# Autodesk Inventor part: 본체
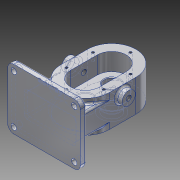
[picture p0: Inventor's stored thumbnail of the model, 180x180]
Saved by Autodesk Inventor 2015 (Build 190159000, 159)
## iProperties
Created: 2020-09
Part Number: 본체
Material: 알루미늄 6061
Document SubType Name: Modeling
Designer: LINEART-SSD.D4.16.06
Density: 2.7 g/cm^3
Appearance: 알루미늄 - 평지
Mass: 1442.27 g
Surface Area: 790.225 cm^2
Volume: 534.173 cm^3
Author: LINEART-SSD.D4.16.06
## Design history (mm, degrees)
sketch "스케치1"
  geometry: L1 (40, 152)-(0, 152); L2 (40, 152)-(80, 152); L3 (40, 90)-(40, 28); L4 (0, 28)-(80, 28); L5 (80, 28)-(80, 152); L6 (80, 152)-(0, 152); L7 (0, 152)-(0, 28); L8 (0, 28)-(80, 152); L9 (80, 28)-(0, 152); 1 further point
  constraints: 18 end point, 3 horizontal, 2 midpoint, 2 parallel, 1 perpendicular
  dimensions: "d7" = 40 distance of L1.start L1.end; "d8" = 40 distance of L1.start L2.end; "d9" = 62 distance of L3.start L3.end
extrude "돌출1" new body sketch "스케치1" distance "d10" = 53; taper "d11" = 0 deg
fillet "모깎기1" dims "d12" = 40
sketch "스케치2"
  geometry: L1 (80, 68)-(80, 112) reference; L2 (0, 112)-(0, 68) reference; L3 (16, 112)-(16, 68); L4 (64, 112)-(64, 68); A1 r 40 centre (40, 68) between (0, 68) and (80, 68) reference; A2 r 40 centre (40, 112) between (80, 112) and (0, 112) reference; A3 r 40 centre (40, 68) between (0, 68) and (80, 68) reference; A4 r 24 centre (40, 112) between (64, 112) and (16, 112); A5 r 24 centre (40, 68) between (16, 68) and (64, 68); 1 further point
  constraints: 4 end point, 4 point on circle, 2 centre point, 2 coincident, 2 tangent
  dimensions: "d40" = 48 diameter of A5
extrude "돌출2" cut sketch "스케치2" distance "d17" = 29; taper "d18" = 0 deg
node "작업 평면1"
sketch "스케치7"
  geometry: L1 (136, 53)-(136, 24) reference; L2 (112, 24)-(136, 24) reference; L3 (124.5, 24)-(124.5, 9); L4 (124.5, 9)-(120.5, 9); L5 (112, 0)-(112, 53) reference; L6 (120.5, 9)-(120.5, -9.7); L7 (120.5, -9.7)-(125.596, -9.7); L8 (112, -25.591)-(112, 0); L9 (126, -17)-(131, -17); L10 (124.5, 24)-(112, 24); L11 (152, 0)-(112, 0) reference; L12 (131, -17)-(131, 0); L13 (131, 0)-(120.5, 0); L14 (112, 24)-(112, 0); L15 (120.5, 0)-(112, 0); L16 (125.596, -9.7)-(126, -10.4); L17 (126, -10.4)-(126, -17); 1 further point
  constraints: 26 end point, 5 perpendicular, 4 point on line, 3 vertical, 1 collinear, 1 horizontal
  dimensions: "d42" = 15 distance between parallel lines of L4 L2; "d43" = 17 distance between parallel lines of L11 L9; "d44" = 7.3 distance between parallel lines of L7 L9; "d48" = 25 diameter of L3 L8; "d49" = 17 diameter of L6 L8; "d51" = 38 diameter of L12 L8; "d120" = 25.59078 distance from line of L8.start L11; "d147" = 0.7 vertical distance of L16.end L7.end; "d148" = 30 deg angle of L17 L16; "d149" = 28 diameter of L17 L8
revolve "회전4" sketch "스케치7" stored, may be unused: angle "d52" = 90 deg
sketch "스케치8"
  geometry: L1 (112, 24)-(136, 24) reference; L2 (120.5, 9)-(120.5, 0); L3 (152, 0)-(112, 0) reference; L4 (112, 24)-(112, 0); L5 (112, 0)-(112, 53) reference; L6 (120.5, 9)-(124.5, 9); L7 (124.5, 9)-(124.5, 24); 1 further point
  constraints: 8 end point, 2 point on line, 1 collinear, 1 horizontal, 1 perpendicular
  dimensions: "d53" = 25 diameter of L7 L4; "d54" = 17 diameter of L2 L4; "d55" = 15 distance between parallel lines of L1 L6
revolve "회전5" sketch "스케치8" stored, may be unused: angle "d56" = 90 deg
sketch "스케치9"
  geometry: L1 (44, 53)-(44, 24) reference; L2 (44, 24)-(68, 24) reference; L3 (56, 24)-(56, 4.58); L4 (68.5, 12.214)-(68.5, 4.58); L5 (68.5, 4.58)-(56, 4.58); L6 (68.5, 12.214)-(68.5, 24); L7 (68.5, 24)-(68, 24); L8 (68, 24)-(112, 24) reference; L9 (68, 24)-(68.5, 24); L10 (68, 24)-(56, 24); 1 further point
  constraints: 14 end point, 3 collinear, 3 vertical, 1 midpoint, 1 perpendicular
  dimensions: "d58" = 25 diameter of L4 L3; "d121" = 19.41962 distance between parallel lines of L8 L5; "d122" = 11.78565 distance from line of L4.start L2
sketch "스케치10"
  geometry: L1 (64, 112)-(64, 68) reference; L2 (16, 68)-(16, 112) reference; C1 r 12.5 at (40, 112) reference; C2 r 12.5 at (40, 112) reference; A1 r 24 centre (40, 68) between (16, 68) and (64, 68) reference; A2 r 24 centre (40, 112) between (64, 112) and (16, 112) reference; A3 r 31 centre (40, 68) between (9, 68) and (71, 68); 6 further points
  constraints: 3 point on circle, 2 coincident, 1 centre point, 1 vertical alignment
  dimensions: "d61" = 31 distance of C1.centre point (40, 143); "d69" = 31 radius of A3
hole "구멍1" sketch "스케치10" at (40, 143), (71, 112), (9, 112), (9, 68), (71, 68), (40, 37) diameter "d62" = 4.134; stored, may be unused: countersink angle "d66" = 90 deg, drill point angle "d68" = 118 deg; dims "d63" = 10, "d64" = 4, "d65" = 2, "d67" = 12
sketch "스케치11"
  geometry: L1 (0, 0)-(-53, 0) reference; L2 (0, 44)-(0, 0) reference; L3 (-53, 44)-(0, 44) reference; L4 (-53, 0)-(-53, 44) reference; L5 (-53, 0)-(0, 0) reference; L6 (0, 44)-(-53, 44) reference; L7 (0, -40)-(-53, -40) reference; C1 r 11 at (-39, 22); 1 further point
  constraints: 1 centre point
  dimensions: "d90" = 14 distance from line of C1.centre L4; "d91" = 22 distance from line of L1 C1.centre; "d92" = 22 diameter of C1
extrude "돌출3" join sketch "스케치11" distance "d72" = 10; taper "d73" = 0 deg
sketch "스케치12"
  geometry: L1 (53, 0)-(0, 0) reference; L2 (53, 44)-(53, 0) reference; L3 (0, 44)-(53, 44) reference; L4 (0, 0)-(0, 44) reference; C1 r 11 at (39, 22); 2 further points
  constraints: 1 centre point, 1 midpoint
  dimensions: "d93" = 14 distance from line of L2 C1.centre; "d94" = 22 distance from line of L1 C1.centre; "d95" = 22 diameter of C1
extrude "돌출4" join sketch "스케치12" distance "d77" = 10; taper "d78" = 0 deg
sketch "스케치16"
  geometry: L1 (68, 53)-(68, 53) reference; L2 (68, 53)-(68, 0) reference; L3 (68, 0)-(68, 0) reference; L4 (68, 0)-(68, 53) reference; L5 (68, 24)-(112, 24) reference; L6 (68, 24)-(80.5, 24); L7 (80.5, 24)-(80.5, 9); L8 (80.5, 9)-(68, 9); L9 (68, 24)-(68, 9); 1 further point
  constraints: 8 end point, 2 point on line, 1 collinear, 1 perpendicular, 1 vertical
  dimensions: "d109" = 15 distance between parallel lines of L5 L8; "d110" = 25 diameter of L7 L2
revolve "회전6" sketch "스케치16" stored, may be unused: angle "d111" = 90 deg
sketch "스케치17"
  geometry: L1 (0, 53)-(-80, 53) reference; L2 (-80, 53)-(-80, 0) reference; L3 (-80, 0)-(0, 0) reference; L4 (0, 0)-(0, 53) reference; L5 (-40, 53)-(-40, -17.335); L6 (-40, -17.335)-(-40, 44.665); L7 (-40, 44.665)-(-40, 82.665); L8 (-40, -17.335)-(20, -17.335); L9 (20, -17.335)-(20, 82.665); L10 (20, 82.665)-(-40, 82.665); L11 (-40, 82.665)-(-100, 82.665); L12 (-100, 82.665)-(-100, -17.335); L13 (-100, -17.335)-(-40, -17.335); 1 further point
  constraints: 18 end point, 2 horizontal, 2 perpendicular, 2 point on line, 1 midpoint, 1 vertical
  dimensions: "d112" = 62 distance of L5.end L6.end; "d113" = 38 distance of L6.end L7.end; "d114" = 60 distance of L5.end L8.end; "d115" = 100 distance of L8.end L9.end; "d116" = 60 distance of L7.end L11.end; "d117" = 100 distance of L11.end L12.end; "d123" = 17.33463 distance between parallel lines of L3 L8
extrude "돌출7" join sketch "스케치17" distance "d118" = 10; taper "d119" = 0 deg
fillet "모깎기3" dims "d124" = 3, "d125" = 10
sketch "스케치18"
  geometry: L1 (97, 7.335)-(97, -72.665) reference; L2 (-10, 14.335)-(90, 14.335) reference; L3 (-17, -72.665)-(-17, 7.335) reference; L4 (90, -79.665)-(-10, -79.665) reference; C1 r 4.5 at (-10, -72.665); C2 r 4.5 at (-10, 7.335); C3 r 4.5 at (90, -72.665); C4 r 4.5 at (90, 7.335); A1 r 7 centre (-10, -72.665) between (-17, -72.665) and (-10, -79.665) reference; A2 r 7 centre (90, -72.665) between (90, -79.665) and (97, -72.665) reference; A3 r 7 centre (90, 7.335) between (97, 7.335) and (90, 14.335) reference; A4 r 7 centre (-10, 7.335) between (-10, 14.335) and (-17, 7.335) reference; A5 r 7 centre (-10, -72.665) between (-17, -72.665) and (-10, -79.665) reference; 1 further point
  constraints: 4 centre point, 4 coincident
  dimensions: "d126" = 9 diameter of C1; "d127" = 9 diameter of C2; "d128" = 9 diameter of C3; "d129" = 9 diameter of C4
extrude "돌출8" cut sketch "스케치18" distance "d130" = 10; taper "d131" = 0 deg
node "작업 평면2"
sketch "스케치19"
  geometry: L1 (0, 10)-(100, 10) reference; L2 (100, 0)-(0, 0) reference; L3 (50, 0)-(10, 0); L4 (50, 0)-(90, 0); L5 (90, 0)-(90, 68); L6 (10, 68)-(10, 0); A1 r 40 centre (50, 68) between (10, 68) and (90, 68) reference; A2 r 40 centre (50, 68) between (10, 68) and (90, 68)
  constraints: 8 end point, 2 point on circle, 1 centre point, 1 coincident, 1 collinear, 1 midpoint, 1 perpendicular, 1 point on line, 1 tangent
  dimensions: "d133" = 40 distance of L3.start L3.end; "d134" = 40 distance of L3.start L4.end (derived)
extrude "돌출9" join sketch "스케치19" distance "d135" = 37; taper "d136" = 0 deg
sketch "스케치20"
  geometry: C1 r 11 at (0, 0) reference; 2 further points
  constraints: 1 coincident
hole "구멍3" sketch "스케치20" at (0, 0) diameter "d137" = 8.376; stored, may be unused: countersink angle "d141" = 90 deg, drill point angle "d143" = 118 deg; dims "d138" = 20, "d139" = 4, "d140" = 2, "d142" = 27.3
fillet "모깎기4" dims "d144" = 3
fillet "모깎기5" dims "d145" = 3
fillet "모깎기6" dims "d146" = 3
chamfer "모따기1" distance "d150" = 1; stored, may be unused: second distance "d151" = 2, angle "d152" = 45 deg
sketch "스케치21"
  geometry: L1 (-10, -82.665)-(90, -82.665) reference; L2 (-20, 7.335)-(-20, -72.665) reference; 2 further points
  constraints: 1 other
  dimensions: "d153" = 12 distance from line of L1 point (40, -70.665); "d154" = 60 distance from line of L2 point (40, -70.665)
feature "엠보싱1" sketch "스케치21" dims "d7" = 40, "d8" = 40, "d9" = 62, "d155" = 0.5, "d156" = 0
node "솔리드1"
node "투영된 루프1"
node "투영된 루프3"
node "투영된 루프4"
node "투영된 루프5"
node "투영된 루프9"
node "투영된 루프10"
node "투영된 루프11"
node "투영된 루프12"
other parameters: "d132" = -25
